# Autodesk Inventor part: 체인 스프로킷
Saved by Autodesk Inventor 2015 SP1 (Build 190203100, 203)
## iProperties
Created: 2026-07
Part Number: 체인 스프로킷
Material: 일반
Document SubType Name: Modeling
Designer: user
Density: 1 g/cm^3
Appearance: 기본값
Author: user
Author: jhkim
Creation Date: 2026-07-01
Sending System: Autodesk Inventor 2027
Preprocessor: ST-DEVELOPER v20.1
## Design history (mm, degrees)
node "체인 스프로킷1"
body "Solid1"
node "기준1"
